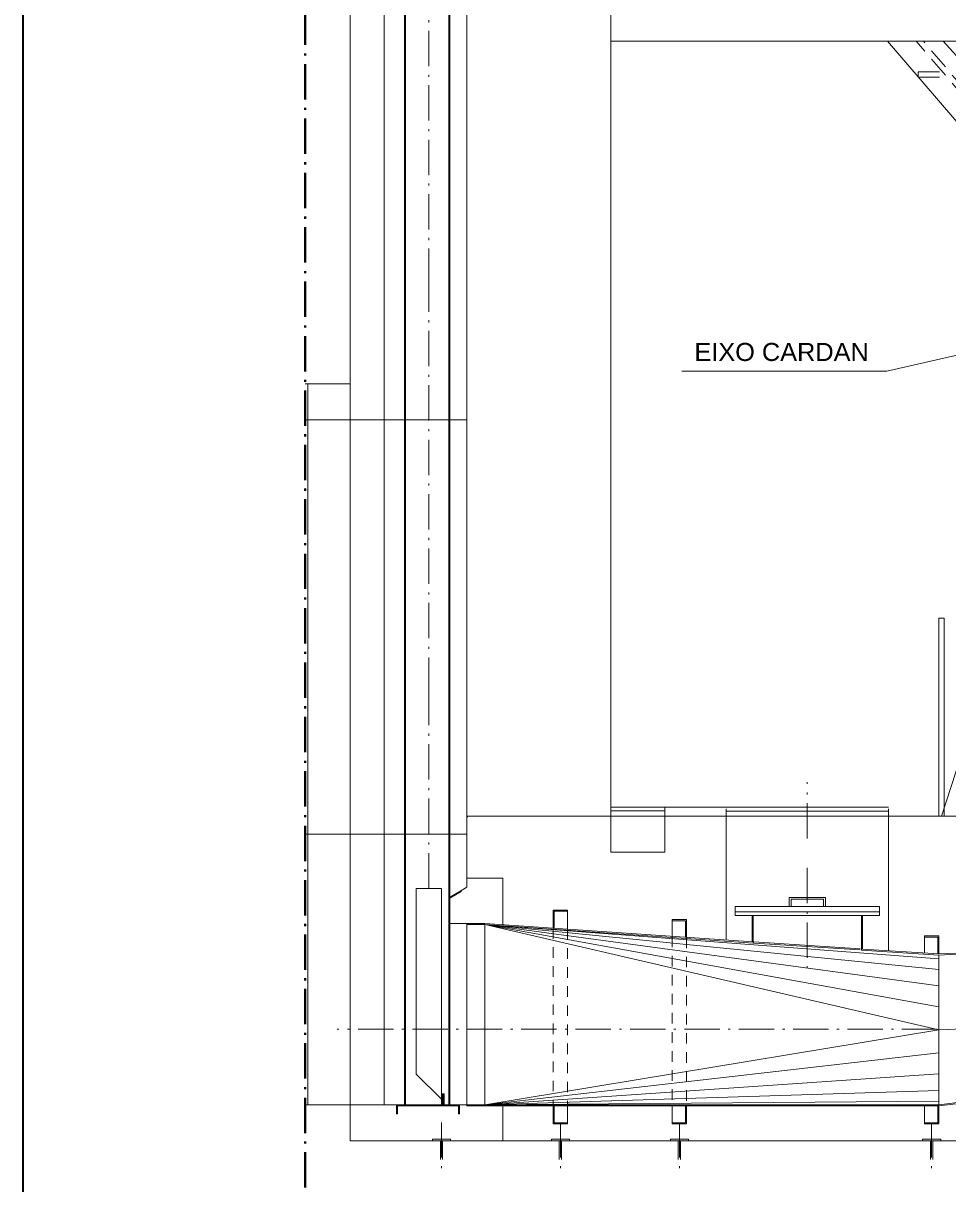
# Model space of a CAD drawing. Extents: x -4160 to -2690, y -474 to 714.
# Drawn here: x -3714.8 to -3641.5, y -425.7 to -333.7 of the extents above; entities that cross this region are included whole.
import ezdxf
from ezdxf.enums import TextEntityAlignment as Align

# ---------------------------------------------------------------- set-up
doc = ezdxf.new("R2010")
doc.units = 0
doc.header["$LTSCALE"] = 0.56
for name, pattern in [('DOT_DASHED', [7.7, 5, -1.2, 0.3, -1.2]), ('MEDIUM_DASHED', [4.5, 3, -1.5]), ('SHORT_DASHED', [2.7, 1.5, -1.2])]:
    doc.linetypes.add(name, pattern=pattern)
for name, color, linetype, lineweight in [('10', 7, 'Continuous', 35), ('11', 7, 'Continuous', 13), ('12', 7, 'Continuous', 13), ('13', 7, 'Continuous', 13), ('14', 7, 'Continuous', 13), ('16', 7, 'Continuous', 13), ('19', 7, 'MEDIUM_DASHED', 13), ('2', 7, 'Continuous', 25), ('3', 7, 'Continuous', 13), ('4', 7, 'Continuous', 25), ('5', 7, 'Continuous', 35), ('63', 7, 'Continuous', 13), ('7', 7, 'DOT_DASHED', 13), ('8', 7, 'Continuous', 13), ('9', 7, 'Continuous', 13)]:
    doc.layers.add(name, color=color, linetype=linetype, lineweight=lineweight)

msp = doc.modelspace()

# ---------------------------------------------------------------- linework, layer by layer
at = {"layer": '10', "lineweight": 13}
for p, q in [((-3646.2427, -335.144), (-3630.1756, -353.8883)), ((-3641.8313, -335.144), (-3630.1756, -348.0483)), ((-3681.0327, -404.6297), (-3681.0327, -419.4297)), ((-3680.947, -404.6297), (-3680.947, -419.4297))]:
    msp.add_line(p, q, dxfattribs=at)
at = {"layer": '10', "linetype": 'MEDIUM_DASHED', "lineweight": 13}
for p, q in [((-3630.1756, -351.2354), (-3643.9684, -335.144)), ((-3630.1756, -350.5769), (-3643.4041, -335.144)), ((-3643.8056, -337.5583), (-3641.8984, -337.5583)), ((-3643.8056, -337.5583), (-3643.8056, -337.9869)), ((-3643.8056, -337.9869), (-3641.5313, -337.9869))]:
    msp.add_line(p, q, dxfattribs=at)
at = {"layer": '11'}
for p, q in [((-3668.1756, -335.144), (-3643.747, -335.144)), ((-3679.6041, -386.7754), (-3679.6041, -354.3712)), ((-3679.6041, -401.4868), (-3679.6041, -386.7754)), ((-3668.1756, -396.5725), (-3573.8899, -396.5725)), ((-3692.4141, -419.4297), (-3685.1755, -419.4297))]:
    msp.add_line(p, q, dxfattribs=at)
at = {"layer": '11', "linetype": 'SHORT_DASHED'}
for p, q in [((-3672.7484, -405.434), (-3672.7484, -419.5154)), ((-3671.6055, -405.5125), (-3671.6055, -419.5154)), ((-3663.3184, -406.1154), (-3663.3184, -419.5154)), ((-3662.177, -406.1897), (-3662.177, -419.5154))]:
    msp.add_line(p, q, dxfattribs=at)
at = {"layer": '11'}
msp.add_lwpolyline([(-3679.6041, -354.3712), (-3679.6041, -287.7526), (-3679.6041, -262.287)], dxfattribs=at)
at = {"layer": '12'}
for p, q in [((-3668.1756, -396.5725), (-3679.6041, -396.5725)), ((-3688.8327, -419.4297), (-3688.8327, -422.2868))]:
    msp.add_line(p, q, dxfattribs=at)
at = {"layer": '13'}
for p, q in [((-3688.8327, -386.7754), (-3688.8327, -287.7526)), ((-3643.747, -335.144), (-3630.1756, -335.144)), ((-3686.1555, -386.7754), (-3686.1555, -354.3712)), ((-3692.4141, -362.2869), (-3688.8327, -362.2869)), ((-3688.8327, -419.4297), (-3688.8327, -386.7754)), ((-3686.1555, -419.4297), (-3686.1555, -386.7754))]:
    msp.add_line(p, q, dxfattribs=at)
msp.add_lwpolyline([(-3686.1555, -354.3712), (-3686.1555, -287.7526), (-3686.1555, -265.1441)], dxfattribs=at)
at = {"layer": '14'}
for p, q in [((-3692.1955, -386.7754), (-3692.1955, -362.2869)), ((-3692.1955, -419.4297), (-3692.1955, -386.7754))]:
    msp.add_line(p, q, dxfattribs=at)
at = {"layer": '16'}
msp.add_line((-3679.6041, -396.6697), (-3679.5084, -396.5725), dxfattribs=at)
at = {"layer": '19', "linetype": 'Continuous'}
for p, q in [((-3692.4141, -365.144), (-3679.6041, -365.144)), ((-3692.4141, -398.0011), (-3679.6041, -398.0011))]:
    msp.add_line(p, q, dxfattribs=at)
at = {"layer": '3'}
for p, q in [((-3658.3184, -403.7155), (-3658.3184, -404.4297)), ((-3658.3184, -403.7155), (-3646.8898, -403.7155)), ((-3654.0326, -403.0012), (-3654.0326, -403.7155)), ((-3653.8898, -403.144), (-3653.8898, -403.7155)), ((-3653.8898, -403.144), (-3651.3184, -403.144)), ((-3651.3184, -403.144), (-3651.3184, -403.7155)), ((-3646.8898, -403.7155), (-3646.8898, -404.4297)), ((-3658.3184, -404.144), (-3646.8898, -404.144)), ((-3658.3184, -404.4297), (-3646.8898, -404.4297)), ((-3656.9755, -404.4297), (-3656.9755, -406.5269)), ((-3656.8898, -404.4297), (-3656.8898, -406.6183)), ((-3648.3184, -404.4297), (-3648.3184, -407.174)), ((-3648.2327, -404.4297), (-3648.2327, -407.094)), ((-3679.604, -405.0583), (-3678.1755, -405.0583)), ((-3679.604, -405.144), (-3679.604, -405.0583)), ((-3679.604, -405.144), (-3679.604, -419.4297)), ((-3679.604, -405.144), (-3678.1755, -405.144)), ((-3678.1755, -405.0583), (-3656.8841, -406.5326)), ((-3678.1755, -405.144), (-3678.1755, -405.0583)), ((-3678.1755, -405.144), (-3678.1755, -419.4297)), ((-3678.1755, -405.144), (-3656.8898, -406.6183)), ((-3656.8484, -406.5355), (-3648.4055, -407.0826)), ((-3656.8312, -406.6212), (-3648.4055, -407.1683)), ((-3648.3184, -407.174), (-3642.1755, -407.5726)), ((-3648.2327, -407.094), (-3642.1755, -407.4869)), ((-3640.8527, -407.4269), (-3642.1755, -407.4869)), ((-3640.8384, -407.5126), (-3642.1755, -407.5726)), ((-3642.1755, -407.5726), (-3642.1755, -419.4297)), ((-3679.604, -419.4297), (-3642.1755, -419.4297)), ((-3679.604, -419.4297), (-3679.604, -419.5154)), ((-3638.5527, -419.0012), (-3642.1755, -419.4297)), ((-3638.5355, -419.0854), (-3642.1712, -419.5154)), ((-3679.604, -419.5154), (-3642.1712, -419.5154))]:
    msp.add_line(p, q, dxfattribs=at)
msp.add_lwpolyline([(-3654.0326, -403.0012), (-3651.1755, -403.0012), (-3651.1755, -403.7155)], dxfattribs=at)
at = {"layer": '4', "lineweight": 13}
for p, q in [((-3668.1755, -396.5726), (-3679.604, -396.5726)), ((-3663.8898, -396.5726), (-3659.0326, -396.5726)), ((-3663.8898, -396.5726), (-3663.8898, -399.4297)), ((-3659.0326, -396.5726), (-3659.0326, -406.3926)), ((-3646.1755, -396.5726), (-3634.6955, -396.5726)), ((-3646.1755, -396.5726), (-3646.1755, -407.2269)), ((-3668.1755, -399.4297), (-3663.8898, -399.4297)), ((-3679.604, -405.0583), (-3680.9469, -405.0583)), ((-3688.8326, -419.4297), (-3688.8326, -422.2869)), ((-3680.1755, -419.4297), (-3679.604, -419.4297)), ((-3676.7469, -419.4297), (-3676.7469, -422.2869)), ((-3688.8326, -422.2869), (-3672.8912, -422.2869)), ((-3671.4626, -422.2869), (-3620.4612, -422.2869))]:
    msp.add_line(p, q, dxfattribs=at)
at = {"layer": '5', "linetype": 'DOT_DASHED', "lineweight": 13}
for p, q in [((-3682.604, -354.3712), (-3682.604, -262.287)), ((-3682.604, -386.7755), (-3682.604, -354.3712)), ((-3682.604, -402.2869), (-3682.604, -386.7755))]:
    msp.add_line(p, q, dxfattribs=at)
at = {"layer": '5'}
msp.add_lwpolyline([(-3714.764, -463.5197), (-3714.764, -210.5199), (-3540.7642, -210.5199), (-3540.7642, -463.5197)], close=True, dxfattribs=at)
at = {"layer": '63'}
for p, q in [((-3668.1756, -330.144), (-3668.1756, -335.144)), ((-3668.1756, -399.4297), (-3668.1756, -335.144)), ((-3642.1756, -396.5725), (-3642.1756, -380.8583)), ((-3642.1756, -380.8583), (-3641.747, -380.8583)), ((-3641.747, -396.5725), (-3641.747, -380.8583)), ((-3676.747, -401.4868), (-3679.6041, -401.4868)), ((-3679.6041, -401.4868), (-3679.6041, -402.2011)), ((-3676.747, -401.4868), (-3676.747, -405.1568)), ((-3683.6041, -402.2868), (-3683.6041, -417.0011)), ((-3683.6041, -402.2868), (-3681.6041, -402.2868)), ((-3681.6041, -402.2868), (-3681.6041, -419.4297)), ((-3680.0755, -402.4725), (-3681.0327, -403.0254)), ((-3680.737, -402.954), (-3680.7998, -402.8911)), ((-3680.7213, -402.944), (-3680.7841, -402.8811)), ((-3680.7055, -402.9354), (-3680.7684, -402.8725)), ((-3680.6884, -402.9254), (-3680.7513, -402.864)), ((-3680.6727, -402.9168), (-3680.7355, -402.854)), ((-3680.657, -402.9082), (-3680.7198, -402.8454)), ((-3680.6413, -402.8982), (-3680.7041, -402.8354)), ((-3680.6255, -402.8897), (-3680.6884, -402.8268)), ((-3680.6084, -402.8797), (-3680.6713, -402.8168)), ((-3680.5927, -402.8711), (-3680.6555, -402.8082)), ((-3680.577, -402.8611), (-3680.6398, -402.7982)), ((-3680.5613, -402.8525), (-3680.6241, -402.7897)), ((-3680.5455, -402.8425), (-3680.6084, -402.7797)), ((-3680.5284, -402.834), (-3680.5913, -402.7711)), ((-3680.5127, -402.824), (-3680.5755, -402.7611)), ((-3680.497, -402.8154), (-3680.5598, -402.7525)), ((-3680.4813, -402.8054), (-3680.5441, -402.7425)), ((-3680.4655, -402.7968), (-3680.527, -402.734)), ((-3680.4484, -402.7868), (-3680.5113, -402.724)), ((-3680.4327, -402.7782), (-3680.4955, -402.7154)), ((-3680.417, -402.7682), (-3680.4798, -402.7068)), ((-3680.4013, -402.7597), (-3680.4641, -402.6968)), ((-3680.3855, -402.7511), (-3680.447, -402.6882)), ((-3680.3684, -402.7411), (-3680.4313, -402.6782)), ((-3680.3527, -402.7325), (-3680.4155, -402.6697)), ((-3680.337, -402.7225), (-3680.3998, -402.6597)), ((-3680.3213, -402.714), (-3680.3841, -402.6511)), ((-3680.3041, -402.704), (-3680.367, -402.6411)), ((-3680.2884, -402.6954), (-3680.3513, -402.6325)), ((-3680.2727, -402.6854), (-3680.3355, -402.6225)), ((-3680.257, -402.6768), (-3680.3198, -402.614)), ((-3680.2413, -402.6668), (-3680.3041, -402.604)), ((-3680.2241, -402.6582), (-3680.287, -402.5954)), ((-3680.2084, -402.6482), (-3680.2713, -402.5854)), ((-3680.1927, -402.6397), (-3680.2555, -402.5768)), ((-3680.177, -402.6297), (-3680.2398, -402.5668)), ((-3680.1613, -402.6211), (-3680.2241, -402.5582)), ((-3680.1441, -402.6111), (-3680.207, -402.5497)), ((-3680.1284, -402.6025), (-3680.1913, -402.5397)), ((-3680.1127, -402.594), (-3680.1755, -402.5311)), ((-3680.097, -402.584), (-3680.1598, -402.5211)), ((-3680.0813, -402.5754), (-3680.1427, -402.5125)), ((-3680.0641, -402.5654), (-3680.127, -402.5025)), ((-3680.0484, -402.5568), (-3680.1113, -402.494)), ((-3680.0327, -402.5468), (-3680.0955, -402.484)), ((-3680.0755, -402.4725), (-3679.6041, -402.2011)), ((-3680.0327, -402.5468), (-3680.0755, -402.4725)), ((-3681.0327, -403.0254), (-3681.0327, -404.6297)), ((-3680.947, -403.1225), (-3681.0327, -403.0368)), ((-3680.947, -403.1468), (-3681.0327, -403.0611)), ((-3680.947, -403.1725), (-3681.0327, -403.0868)), ((-3680.947, -403.1982), (-3681.0327, -403.1125)), ((-3680.947, -403.2225), (-3681.0327, -403.1368)), ((-3680.947, -403.2482), (-3681.0327, -403.1625)), ((-3680.947, -403.274), (-3681.0327, -403.1882)), ((-3680.947, -403.2982), (-3681.0327, -403.2125)), ((-3680.947, -403.324), (-3681.0327, -403.2382)), ((-3680.947, -403.3497), (-3681.0327, -403.264)), ((-3680.947, -403.374), (-3681.0327, -403.2882)), ((-3680.947, -403.3997), (-3681.0327, -403.314)), ((-3680.947, -403.4254), (-3681.0327, -403.3397)), ((-3680.947, -403.4497), (-3681.0327, -403.364)), ((-3680.947, -403.4754), (-3681.0327, -403.3897)), ((-3680.947, -403.5011), (-3681.0327, -403.4154)), ((-3680.947, -403.5254), (-3681.0327, -403.4397)), ((-3680.947, -403.5511), (-3681.0327, -403.4654)), ((-3680.947, -403.5768), (-3681.0327, -403.4911)), ((-3680.947, -403.6025), (-3681.0327, -403.5168)), ((-3680.947, -403.6268), (-3681.0327, -403.5411)), ((-3680.947, -403.6525), (-3681.0327, -403.5668)), ((-3680.947, -403.6782), (-3681.0327, -403.5925)), ((-3680.947, -403.7025), (-3681.0327, -403.6168)), ((-3680.947, -403.7282), (-3681.0327, -403.6425)), ((-3680.947, -403.754), (-3681.0327, -403.6682)), ((-3680.947, -403.7782), (-3681.0327, -403.6925)), ((-3680.947, -403.804), (-3681.0327, -403.7182)), ((-3680.947, -403.8297), (-3681.0327, -403.744)), ((-3680.947, -403.854), (-3681.0327, -403.7682)), ((-3680.947, -403.8797), (-3681.0327, -403.794)), ((-3680.947, -403.0968), (-3681.0241, -403.0211)), ((-3680.9455, -403.074), (-3681.0084, -403.0111)), ((-3680.9298, -403.0654), (-3680.9913, -403.0025)), ((-3680.9127, -403.0554), (-3680.9755, -402.9925)), ((-3680.897, -403.0468), (-3680.9598, -402.984)), ((-3680.8813, -403.0368), (-3680.9441, -402.974)), ((-3680.8655, -403.0282), (-3680.9284, -402.9654)), ((-3680.8498, -403.0182), (-3680.9113, -402.9554)), ((-3680.8327, -403.0097), (-3680.8955, -402.9468)), ((-3680.817, -402.9997), (-3680.8798, -402.9368)), ((-3680.8013, -402.9911), (-3680.8641, -402.9282)), ((-3680.7855, -402.9811), (-3680.8484, -402.9182)), ((-3680.7684, -402.9725), (-3680.8313, -402.9097)), ((-3680.7527, -402.9625), (-3680.8155, -402.8997)), ((-3680.947, -403.9054), (-3681.0327, -403.8197)), ((-3680.947, -403.9297), (-3681.0327, -403.844)), ((-3680.947, -403.9554), (-3681.0327, -403.8697)), ((-3680.947, -403.9811), (-3681.0327, -403.8954)), ((-3680.947, -404.0054), (-3681.0327, -403.9197)), ((-3680.947, -404.0311), (-3681.0327, -403.9454)), ((-3680.947, -404.0568), (-3681.0327, -403.9711)), ((-3680.947, -404.0811), (-3681.0327, -403.9954)), ((-3680.947, -404.1068), (-3681.0327, -404.0211)), ((-3680.947, -404.1325), (-3681.0327, -404.0468)), ((-3680.947, -404.1568), (-3681.0327, -404.0711)), ((-3680.947, -404.1825), (-3681.0327, -404.0968)), ((-3680.947, -404.2082), (-3681.0327, -404.1225)), ((-3680.947, -404.2325), (-3681.0327, -404.1468)), ((-3680.947, -404.2582), (-3681.0327, -404.1725)), ((-3680.947, -404.284), (-3681.0327, -404.1982)), ((-3680.947, -404.3097), (-3681.0327, -404.224)), ((-3680.947, -404.334), (-3681.0327, -404.2482)), ((-3680.947, -404.3597), (-3681.0327, -404.274)), ((-3680.947, -404.3854), (-3681.0327, -404.2997)), ((-3680.947, -404.4097), (-3681.0327, -404.324)), ((-3680.947, -404.4354), (-3681.0327, -404.3497)), ((-3680.947, -404.4611), (-3681.0327, -404.3754)), ((-3680.947, -404.4854), (-3681.0327, -404.3997)), ((-3680.947, -404.5111), (-3681.0327, -404.4254)), ((-3680.947, -404.5368), (-3681.0327, -404.4511)), ((-3680.947, -404.5611), (-3681.0327, -404.4754)), ((-3680.947, -404.5868), (-3681.0327, -404.5011)), ((-3680.947, -404.6368), (-3681.0327, -404.5511)), ((-3680.9798, -404.6297), (-3681.0327, -404.5768)), ((-3681.0055, -404.6297), (-3681.0327, -404.6025)), ((-3680.947, -404.6297), (-3681.0327, -404.6297)), ((-3672.7484, -405.434), (-3672.7484, -404.0054)), ((-3671.6055, -404.0054), (-3672.7484, -404.0054)), ((-3672.6627, -405.4397), (-3672.6627, -404.0911)), ((-3671.6055, -404.0911), (-3672.6627, -404.0911)), ((-3671.6055, -404.0054), (-3671.6055, -404.0911)), ((-3671.6055, -404.0911), (-3671.6055, -405.5082)), ((-3663.3198, -404.7611), (-3662.177, -404.7611)), ((-3663.3198, -404.8468), (-3662.2627, -404.8468)), ((-3662.2627, -406.1897), (-3662.2627, -404.8468)), ((-3662.177, -406.1897), (-3662.177, -404.7611)), ((-3643.3184, -406.0582), (-3643.3184, -406.144)), ((-3643.3184, -406.0582), (-3642.1756, -406.0582)), ((-3643.3184, -406.144), (-3643.3184, -407.4125)), ((-3643.3184, -406.144), (-3642.2613, -406.144)), ((-3642.2613, -407.4868), (-3642.2613, -406.144)), ((-3642.1756, -407.4868), (-3642.1756, -406.0582)), ((-3681.6041, -419.0011), (-3683.6041, -417.0011)), ((-3685.1755, -419.4297), (-3680.1755, -419.4297)), ((-3685.1755, -419.4297), (-3685.1755, -420.1439)), ((-3681.6041, -418.7468), (-3681.4313, -418.5725)), ((-3681.6041, -418.6197), (-3681.557, -418.5725)), ((-3681.6041, -418.8725), (-3681.3898, -418.6582)), ((-3681.6041, -418.9997), (-3681.3898, -418.7854)), ((-3681.6041, -419.1254), (-3681.3898, -418.9111)), ((-3681.6041, -419.2511), (-3681.3898, -419.0368)), ((-3681.6041, -419.3782), (-3681.3898, -419.1639)), ((-3681.5298, -419.4297), (-3681.3898, -419.2897)), ((-3680.1755, -419.4297), (-3680.1755, -420.1439)), ((-3685.1755, -420.1439), (-3685.0898, -420.1439)), ((-3685.0898, -419.5154), (-3685.0898, -420.1439)), ((-3685.0898, -419.5154), (-3680.2613, -419.5154)), ((-3680.2613, -419.5154), (-3680.2613, -420.1439)), ((-3680.2613, -420.1439), (-3680.1755, -420.1439)), ((-3672.7484, -419.5154), (-3672.7484, -420.9439)), ((-3672.6627, -419.5154), (-3672.6627, -420.8582)), ((-3663.3184, -419.5154), (-3663.3184, -420.8582)), ((-3662.2613, -419.5154), (-3662.2613, -420.8582)), ((-3662.1756, -419.5154), (-3662.1756, -420.9439)), ((-3643.3184, -419.5154), (-3643.3184, -420.8582)), ((-3642.2613, -419.5154), (-3642.2613, -420.8582)), ((-3642.1756, -419.5154), (-3642.1756, -420.9439)), ((-3671.6055, -420.9439), (-3672.7484, -420.9439)), ((-3671.6055, -420.8582), (-3672.6627, -420.8582)), ((-3663.3184, -420.8582), (-3662.2613, -420.8582)), ((-3663.3184, -420.9439), (-3663.3184, -420.8582)), ((-3663.3184, -420.9439), (-3662.1756, -420.9439)), ((-3643.3184, -420.9439), (-3642.1756, -420.9439)), ((-3682.3184, -422.1725), (-3682.3184, -422.2868)), ((-3682.3184, -422.1725), (-3680.8898, -422.1725)), ((-3680.8898, -422.1725), (-3680.8898, -422.2868)), ((-3672.8913, -422.1725), (-3671.4627, -422.1725)), ((-3672.8913, -422.1725), (-3672.8913, -422.2868)), ((-3671.4627, -422.1725), (-3671.4627, -422.2868)), ((-3663.4613, -422.1725), (-3663.4613, -422.2868)), ((-3663.4613, -422.1725), (-3662.0327, -422.1725)), ((-3662.0327, -422.1725), (-3662.0327, -422.2868)), ((-3643.4613, -422.1725), (-3643.4613, -422.2868)), ((-3643.4613, -422.1725), (-3642.0327, -422.1725)), ((-3642.0327, -422.1725), (-3642.0327, -422.2868)), ((-3682.3184, -422.2868), (-3680.8898, -422.2868)), ((-3681.6955, -422.2868), (-3681.6955, -423.7768)), ((-3681.5141, -422.2868), (-3681.5141, -423.7768)), ((-3672.8913, -422.2868), (-3671.4627, -422.2868)), ((-3672.267, -422.2868), (-3672.267, -423.7768)), ((-3672.0855, -422.2868), (-3672.0855, -423.7768)), ((-3663.4613, -422.2868), (-3662.0327, -422.2868)), ((-3662.8384, -422.2868), (-3662.8384, -423.7768)), ((-3662.657, -422.2868), (-3662.657, -423.7768)), ((-3643.4613, -422.2868), (-3642.0327, -422.2868)), ((-3642.8384, -422.2868), (-3642.8384, -423.7768)), ((-3642.657, -422.2868), (-3642.657, -423.7768))]:
    msp.add_line(p, q, dxfattribs=at)
for points in [[(-3662.5456, -361.3), (-3646.3051, -361.3), (-3630.1957, -357.6297)], [(-3680.0327, -402.5468), (-3680.947, -403.0754), (-3680.947, -404.6297)], [(-3663.3198, -404.7611), (-3663.3198, -404.8468), (-3663.3198, -406.1154)], [(-3681.6041, -418.5725), (-3681.3898, -418.5725), (-3681.3898, -419.4297)], [(-3671.6055, -420.9439), (-3671.6055, -420.8582), (-3671.6055, -419.5154)], [(-3643.3184, -420.9439), (-3643.3184, -420.8582), (-3642.2613, -420.8582)]]:
    msp.add_lwpolyline(points, dxfattribs=at)
at = {"layer": '7'}
for p, q in [((-3652.6041, -398.324), (-3652.6041, -393.8597)), ((-3652.6041, -400.6683), (-3652.6041, -408.6582)), ((-3642.2999, -413.454), (-3689.867, -413.454)), ((-3681.6041, -420.8297), (-3681.6041, -424.4825)), ((-3672.177, -420.8297), (-3672.177, -424.4825)), ((-3662.747, -420.8297), (-3662.747, -424.4825)), ((-3642.747, -420.8297), (-3642.747, -424.4825))]:
    msp.add_line(p, q, dxfattribs=at)
msp.add_arc((-3642.1757, -400.787), 12.7143, 270, 0, dxfattribs=at)
at = {"layer": '8'}
for p, q in [((-3668.1756, -395.8583), (-3663.8884, -395.8583)), ((-3668.1756, -396.1354), (-3663.8884, -396.1354)), ((-3663.8898, -396.5725), (-3663.8898, -395.8583)), ((-3663.8884, -395.8583), (-3659.0256, -395.8583)), ((-3659.0327, -396.5725), (-3659.0327, -395.9825)), ((-3658.9998, -395.8583), (-3646.1613, -395.8583)), ((-3658.9998, -396.1568), (-3646.1613, -396.1568)), ((-3646.1756, -396.5725), (-3646.1756, -395.9825)), ((-3668.1756, -396.5725), (-3663.8898, -396.5725)), ((-3659.0327, -396.5725), (-3646.1756, -396.5725)), ((-3642.1756, -411.6697), (-3678.1755, -405.144)), ((-3642.1756, -410.0168), (-3678.1755, -405.144)), ((-3642.1756, -408.7054), (-3678.1755, -405.144)), ((-3642.1756, -407.8625), (-3678.1755, -405.144)), ((-3642.1756, -413.5011), (-3678.1755, -405.144)), ((-3642.1756, -416.9854), (-3678.1755, -419.4297)), ((-3642.1756, -418.2982), (-3678.1755, -419.4297)), ((-3642.1756, -419.1397), (-3678.1755, -419.4297))]:
    msp.add_line(p, q, dxfattribs=at)
msp.add_lwpolyline([(-3642.1756, -415.334), (-3678.1755, -419.4297), (-3642.1756, -413.5011)], dxfattribs=at)
at = {"layer": '9', "linetype": 'DOT_DASHED', "lineweight": 40}
msp.add_line((-3692.4141, -246.3984), (-3692.4141, -446.0525), dxfattribs=at)
at = {"layer": '9'}
for p, q in [((-3684.547, -354.3712), (-3684.547, -386.7754)), ((-3684.4613, -354.3712), (-3684.4613, -386.7754)), ((-3681.0327, -354.3712), (-3681.0327, -386.7754)), ((-3680.947, -386.7754), (-3680.947, -354.3712)), ((-3684.547, -386.7754), (-3684.547, -419.4297)), ((-3684.4613, -386.7754), (-3684.4613, -419.4297)), ((-3681.0327, -386.7754), (-3681.0327, -403.0254)), ((-3680.947, -402.9768), (-3680.947, -386.7754)), ((-3640.4456, -391.8583), (-3641.9556, -396.5725))]:
    msp.add_line(p, q, dxfattribs=at)
for points in [[(-3684.547, -262.287), (-3684.547, -287.7526), (-3684.547, -354.3712)], [(-3684.4613, -262.287), (-3684.4613, -287.7526), (-3684.4613, -354.3712)], [(-3681.0327, -262.287), (-3681.0327, -287.7526), (-3681.0327, -354.3712)], [(-3680.947, -354.3712), (-3680.947, -287.7526), (-3680.947, -262.287)]]:
    msp.add_lwpolyline(points, dxfattribs=at)

# ---------------------------------------------------------------- texts
at = {"layer": '2', "width": 1.05}
msp.add_text('EIXO CARDAN', height=1.429, dxfattribs=at).set_placement((-3654.6428, -360.4861), align=Align.CENTER)

doc.saveas('drawing.dxf')
